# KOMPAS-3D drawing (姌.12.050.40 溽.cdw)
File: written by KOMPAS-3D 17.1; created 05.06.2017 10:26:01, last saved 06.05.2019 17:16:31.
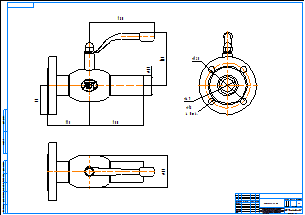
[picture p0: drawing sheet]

Sheet 1: A1, landscape

Title block, sheet 1: name: КШ.12.050.40 фс; material: Внимание! Данный продукт является объектом авторского права ООО «Торговый Дом АДЛ». / Запрещается изменение, копирование, распространение / (в том числе путем копирования на другие сайты и ресурсы в Интернете) / или любое иное использование информации и объектов без предварительного / согласия правообладателя (ООО «Торговый Дом АДЛ»).; sheets: 1; organisation: ООО "Торговый дом АДЛ"; sheet format: A1; stored path: C:\Users\kka\KOMPAS_Work\Модели кранов для исследований\Все краники\Редуцированный резьба-сварка ШК БИВАЛ\КШ.02.015.40 рс.cdw

Views: Вид 1, Проекционный вид 2, Проекционный вид 3
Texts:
  Klimkovich
  ADL
Dimensions and other numbers on the sheet: 148; 180; 57; 115; 150; 80; 125; 49; 18; 4 Отв.; 89; 1:1; 1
